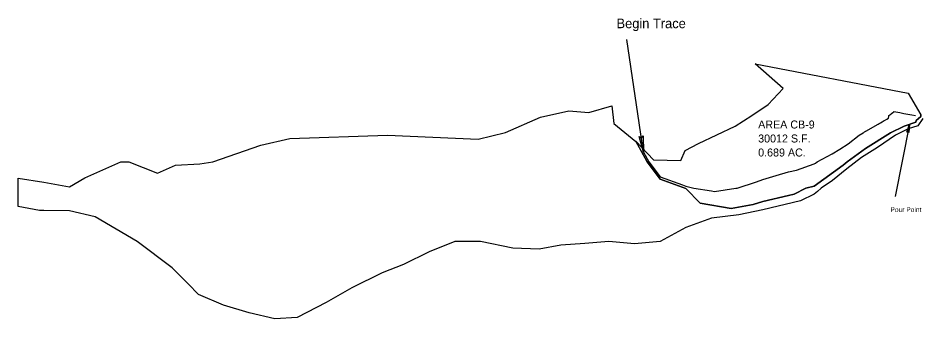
# Model space of a CAD drawing. Extents: x 2238 to 3368, y 2835 to 3212.
import ezdxf

# ---------------------------------------------------------------- set-up
doc = ezdxf.new("R2010")
doc.units = 0
for name, color, linetype in [('Default', 7, 'Continuous'), ('DESIGN - SCRATCH - User 1', 7, 'Continuous'), ('SURVEY - CENTERLINE - Preliminary', 7, 'Continuous'), ('SURVEY - CENTERLINE - Preliminary Text', 7, 'Continuous'), ('SURVEY - DRAINAGE - Area Shapes', 7, 'Continuous')]:
    doc.layers.add(name, color=color, linetype=linetype)

msp = doc.modelspace()

# ---------------------------------------------------------------- linework, layer by layer
at = {"layer": 'DESIGN - SCRATCH - User 1'}
msp.add_line((3351.1, 3078.8), (3333.6, 2988.3), dxfattribs=at)
msp.add_lwpolyline([(3351.1, 3078.8), (3350.4, 3068.6), (3349.4, 3070.2), (3347.9, 3069.1)], close=True, dxfattribs=at)
msp.add_lwpolyline([(3351.1, 3078.8), (3350.4, 3068.6), (3349.4, 3070.2), (3347.9, 3069.1), (3351.1, 3078.8)], dxfattribs=at)
at = {"layer": 'SURVEY - CENTERLINE - Preliminary'}
msp.add_lwpolyline([(3019, 3044), (3025.7, 3031.9), (3039.9, 3013.1), (3067.9, 3002.9), (3072, 3001.5), (3082, 2998.7), (3104.1, 2995.6), (3107.8, 2994.9), (3134.5, 2998.7), (3136.1, 2998.8), (3136.2, 2998.8), (3160.3, 3006.9), (3168.2, 3009.8), (3184.8, 3014.8), (3200.3, 3019.2), (3210.2, 3021.6), (3232.4, 3029.2), (3233.9, 3030.3), (3236.1, 3031.9), (3254.8, 3041.9), (3264.5, 3047.5), (3274.8, 3054.4), (3288.6, 3065.1), (3293.6, 3068), (3293.7, 3068.1), (3293.8, 3068.1), (3294, 3068.3), (3294.4, 3068.5), (3294.8, 3068.8), (3295.3, 3069.2), (3295.9, 3069.7), (3296.5, 3070.1), (3296.9, 3070.3), (3312, 3078.9), (3313.4, 3079.7), (3314.1, 3080.1), (3315.1, 3080.6), (3317.2, 3081.8), (3319.8, 3083.4), (3320.2, 3083.6), (3323.2, 3085.3), (3324.9, 3086.4), (3325.4, 3088.3), (3325.7, 3089.8), (3326.2, 3090.2), (3326.8, 3090.7), (3327.8, 3091.4), (3329, 3092.3), (3330.4, 3093.4), (3331.6, 3094.3), (3331.8, 3094.6), (3331.9, 3094.8), (3331.9, 3094.8), (3331.9, 3094.8), (3334.4, 3094.3), (3339.4, 3093.4), (3344.3, 3092.4), (3349.2, 3091.5), (3354.1, 3090.5), (3359, 3089.6)], dxfattribs=at)
at = {"layer": 'SURVEY - CENTERLINE - Preliminary Text'}
msp.add_line((3019, 3044), (2998.2, 3184.8), dxfattribs=at)
msp.add_lwpolyline([(3019, 3044), (3013.6, 3063.6), (3016.4, 3061.4), (3018.6, 3064.3)], close=True, dxfattribs=at)
msp.add_lwpolyline([(3019, 3044), (3013.6, 3063.6), (3016.4, 3061.4), (3018.6, 3064.3), (3019, 3044)], dxfattribs=at)
at = {"layer": 'SURVEY - DRAINAGE - Area Shapes'}
for p, q in [((3158.5, 3154.4), (3349.8, 3117.8)), ((2950.8, 3093.6), (2979.6, 3101.8))]:
    msp.add_line(p, q, dxfattribs=at)
for points in [[(3193.6, 3123.6), (3158.5, 3154.4)], [(3009.4, 3057.5), (3031.4, 3034.5), (3065.6, 3033.6), (3071.1, 3046.2), (3087.9, 3054.9), (3133.7, 3076.5), (3154.2, 3089.7), (3174.8, 3103.6), (3193.6, 3123.6)], [(3349.8, 3117.8), (3365.4, 3090.4), (3365.5, 3088.4), (3359.5, 3083.4), (3359.1, 3081.4), (3344.7, 3076.6), (3327.4, 3067.9), (3296.5, 3048.3), (3273.4, 3031.9), (3268.5, 3027.7), (3232.4, 3001.4), (3222, 2998.7), (3207.3, 2991.5), (3200.3, 2989.6), (3168.2, 2982.4), (3155.9, 2978.3), (3128.4, 2973.5), (3089.9, 2980.2), (3072, 2998.5), (3039.9, 3010.2), (3023.6, 3031.9), (3009.4, 3057.5)], [(2979.6, 3101.8), (2981.9, 3079.7), (3009.6, 3057.1)], [(2541.2, 3052.5), (2577.3, 3061), (2699.3, 3065), (2812.7, 3060.1), (2846.8, 3068.3), (2890.5, 3087.8), (2925.8, 3095.4), (2950.8, 3093.6)], [(3009.6, 3057.1), (3023.6, 3031.9), (3039.9, 3010.2), (3072, 2998.5), (3089.9, 2980.2), (3128.4, 2973.5), (3155.9, 2978.3), (3168.2, 2982.4), (3200.3, 2989.6), (3207.3, 2991.5), (3222, 2998.7), (3232.4, 3001.4), (3268.5, 3027.7), (3273.4, 3031.9), (3296.5, 3048.3), (3327.4, 3067.9), (3344.7, 3076.6), (3359.1, 3081.4), (3359.5, 3083.4), (3365.5, 3088.4), (3365.4, 3090.4)], [(3368, 3085.9), (3361.7, 3076.9), (3349.8, 3072.9), (3334, 3065.1), (3311.4, 3049.7), (3291.5, 3037.1), (3273.2, 3022.9), (3255, 3008.5), (3240.8, 2998.7), (3236.2, 2994.8), (3232.4, 2991.6), (3215.3, 2983.2), (3168.2, 2971.7)], [(2238, 3011.2), (2270.1, 3006.6), (2302.2, 3000.4), (2321.4, 3012), (2366.3, 3031.9), (2376.5, 3031.9), (2412.1, 3017.7), (2434.5, 3027.7), (2465.1, 3029.2), (2481.1, 3031.9), (2541.2, 3052.5)], [(2450.3, 2879.2), (2430.5, 2899.1), (2386.7, 2932.3), (2334.2, 2962.9), (2302.2, 2970.5), (2270.1, 2971), (2264.9, 2970.9), (2238, 2976.1), (2238, 3011.2)], [(3168.2, 2971.7), (3138.3, 2965.5), (3104.1, 2961.4), (3072, 2949.6), (3039.7, 2932.3), (3007.9, 2929.5), (2975.8, 2932.3), (2946, 2929.9), (2916, 2927.8), (2888.8, 2922.8), (2855.8, 2923.7), (2815.4, 2932.3), (2783.3, 2932.3), (2751.2, 2919.5), (2719.2, 2903.6), (2692.8, 2893.2), (2655, 2874.2), (2622.9, 2856), (2586.7, 2837), (2558.8, 2835.4), (2526.7, 2843), (2494.6, 2852.6), (2463.5, 2865.9), (2450.3, 2879.2)]]:
    msp.add_lwpolyline(points, dxfattribs=at)

# ---------------------------------------------------------------- texts
at = {"layer": 'Default'}
for s, p in [('AREA CB-9', (3162.3, 3073.5)), ('30012 S.F.', (3162.3, 3056)), ('0.689 AC.', (3162.3, 3038.5))]:
    msp.add_text(s, height=10, dxfattribs=at).set_placement(p)
at = {"layer": 'DESIGN - SCRATCH - User 1'}
msp.add_text('Pour Point', height=6, dxfattribs=at).set_placement((3327.5, 2969))
at = {"layer": 'SURVEY - CENTERLINE - Preliminary Text'}
msp.add_text('Begin Trace ', height=12, dxfattribs=at).set_placement((2985.4, 3198.9))

doc.saveas('drawing.dxf')
